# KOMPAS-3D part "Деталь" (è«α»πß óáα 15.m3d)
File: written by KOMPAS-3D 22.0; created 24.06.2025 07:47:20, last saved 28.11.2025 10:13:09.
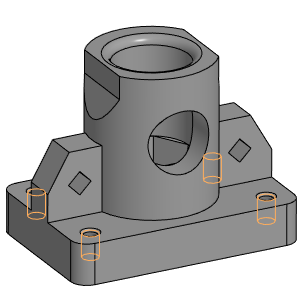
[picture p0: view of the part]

Document properties: Автор: alymovy@yandex.ru; Организация: HP; Полное имя файла: Корпус вар 15.cdw

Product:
- Part/product: Деталь
    Материал: Полипропилен ГОСТ 26996-86 (density 900 kg/m3)
    Масса: 0.478939
    Форматы листов документа: A3

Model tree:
1. Эскиз:1
2. Элемент выдавливания:1
     Расстояние 1 = 25
3. Скругление:1  (with: Элемент выдавливания:1)
     Радиус = 10
4. Эскиз:2  (with: Элемент выдавливания:1)
5. Элемент выдавливания:2
     Расстояние 1 = 85
6. Эскиз:3  (with: Скругление:1, Элемент выдавливания:1)
7. Ребро жесткости:1
     Толщина стенки 1 = 20; Толщина стенки 2 = 1
8. Зеркальный массив:1
9. Экземпляр ( 1 )
10. Экземпляр ( 2 )  (with: Ребро жесткости:1)
11. Эскиз:4  (with: Элемент выдавливания:2)
12. Элемент выдавливания:3
     Расстояние 2 = 60
13. Эскиз:5  (with: Элемент выдавливания:3)
14. Элемент выдавливания:4
     Расстояние 2 = 50
15. Скругление:2  (with: Элемент выдавливания:3)
     Радиус = 5
16. Эскиз:6  (with: Элемент выдавливания:2)
17. Элемент выдавливания:5
     Расстояние 1 = 47.5
18. Эскиз:7  (with: Элемент выдавливания:1)
19. Отверстие:1  (with: Элемент выдавливания:1, Ребро жесткости:1)  (labels: M10)
     Глубина выреза = 20; Диаметр отверстия = 8.3762; Угол конуса дна = 118; Расстояние 1 = -22.5; Расстояние 2 = 15; Диаметр зенковки = 11.5762; Глубина зенковки = 1.6; Угол зенковки = 90
20. M10  (labels: cil0_24705-2004 coarse)
     Длина резьбы = 15; Шаг резьбы = 1.5; Номинальный диаметр резьбы = 10
21. Зеркальный массив:2  (with: Экземпляр ( 1 ), Экземпляр ( 2 ), Отверстие:1)
22. Зеркальный массив:3  (with: Экземпляр ( 1 ), Экземпляр ( 2 ), Зеркальный массив:2, Отверстие:1)
23. Экземпляр ( 2 )  (with: Отверстие:1)
24. Эскиз:8  (with: Ребро жесткости:1, Элемент выдавливания:1)
25. Элемент выдавливания:6
26. Эскиз:9
27. Элемент выдавливания:7  (labels: Полипропилен ГОСТ 26996-86)
     Расстояние 1 = 47.5

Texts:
  Линейный размер с обрывом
